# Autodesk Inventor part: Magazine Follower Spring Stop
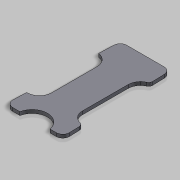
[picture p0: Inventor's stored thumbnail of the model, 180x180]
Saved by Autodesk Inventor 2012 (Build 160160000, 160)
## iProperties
Company: MH Vaaben Teknik
Category: Sten MK II Magazine
Created: 2011-12
Part Number: Magazine Follower Spring Stop
Material: Carbon Steel
Document SubType Name: Modeling
Designer: Michael Høgh
Density: 7.87 g/cm^3
Project: Sten MK II
Engineer: MH Vaaben Teknik
Mass: 2.91641 g
Surface Area: 8.46245 cm^2
Volume: 0.370573 cm^3
Author: Michael Høgh
Title: Magazine Follower Spring Stop
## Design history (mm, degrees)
sketch "Sketch1"
  geometry: L1 (13.887, -0.87)-(2.713, -0.87); L2 (13.887, -0.87)-(2.713, -0.87); L3 (13.068, -10.806)-(13.068, -24.306); L4 (13.068, -10.806)-(13.068, -24.306); L5 (3.813, -10.546)-(3.813, -24.301); L6 (15.816, -2.739)-(15.931, -6.375); L7 (15.931, -6.375)-(15.887, -4.986); L8 (0.644, -7.158)-(0.784, -2.739); L9 (16.637, -28.91)-(16.733, -31.939); L10 (16.666, -29.818)-(16.733, -31.939); L11 (14.804, -33.93)-(12.933, -33.93); L12 (12.933, -33.93)-(14.81, -33.93); L13 (3.954, -33.93)-(1.79, -33.93); L14 (1.79, -33.93)-(3.954, -33.93); L15 (-0.014, -27.967)-(-0.139, -31.939); L16 (-0.139, -31.939)-(-0.072, -29.812); A1 r 3.67 centre (16.738, -10.806) between (14.109, -8.245) and (13.068, -10.806); A2 r 1.93 centre (13.887, -2.8) between (15.816, -2.739) and (13.887, -0.87); A3 r 1.93 centre (2.713, -2.8) between (2.713, -0.87) and (0.784, -2.739); A4 r 1.93 centre (2.713, -2.8) between (2.713, -0.87) and (0.784, -2.739); A5 r 3.701 centre (0.122, -10.822) between (3.813, -10.546) and (0.644, -7.158); A6 r 1.13 centre (14.802, -6.41) between (15.259, -7.444) and (15.931, -6.375); A7 r 4.261 centre (17.087, -11.292) between (15.259, -7.444) and (14.109, -8.245); A8 r 3.49 centre (16.555, -24.438) between (13.068, -24.306) and (15.757, -27.835); A9 r 1.141 centre (15.497, -28.946) between (16.637, -28.91) and (15.757, -27.835); A10 r 1.93 centre (14.804, -32) between (14.804, -33.93) and (16.733, -31.939); A11 r 4.572 centre (8.443, -34.793) between (12.933, -33.93) and (3.954, -33.93); A12 r 1.93 centre (1.79, -32) between (-0.139, -31.939) and (1.79, -33.93); A13 r 1.93 centre (1.79, -32) between (-0.139, -31.939) and (1.79, -33.93); A14 r 3.669 centre (0.144, -24.301) between (-0.014, -27.967) and (3.813, -24.301); 3 further points
  constraints: 33 end point, 28 point on circle, 14 centre point, 13 tangent, 7 collinear, 1 concentric, 1 parallel, 4 other
extrude "Extrusion1" new body sketch "Sketch1" distance "d0" = 1; taper "d1" = 0 deg
body "Solid1"
